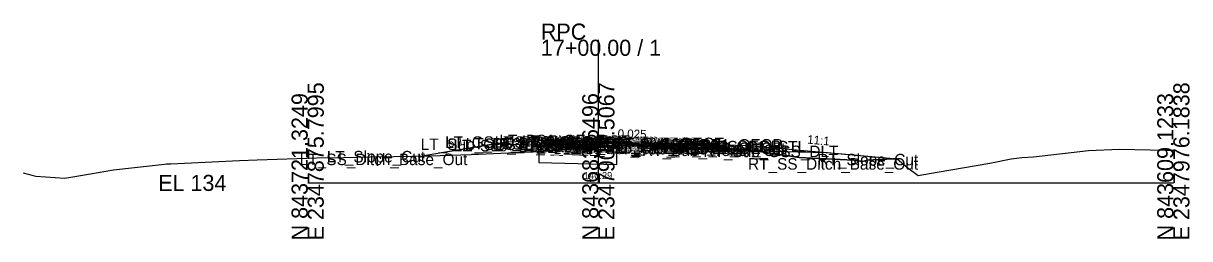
# Model space of a CAD drawing. Extents: x -26 to 203, y -10 to 7538.
# Drawn here: x 0 to 202.8, y 3490.3 to 3527.7 of the extents above; entities that cross this region are included whole.
import ezdxf

# ---------------------------------------------------------------- set-up
doc = ezdxf.new("R2010")
doc.units = 0
for name, color, linetype in [('Default', 7, 'Continuous'), ('Exist CMT Pavement', 7, 'Continuous'), ('Exist Cross Section Cell', 7, 'Continuous'), ('Exist XS Center Line Elevation Label', 7, 'Continuous'), ('Exist XS Ground Line', 7, 'Continuous'), ('Prop CMT Pvmt Course 1', 7, 'Continuous'), ('Prop CMT Pvmt Course 1 Wedge', 7, 'Continuous'), ('Prop CMT Pvmt Course 2', 7, 'Continuous'), ('Prop CMT Pvmt Course 2 Wedge', 7, 'Continuous'), ('Prop CMT Pvmt Course 3', 7, 'Continuous'), ('Prop CMT Pvmt Course 3 Wedge', 7, 'Continuous'), ('Prop CMT Pvmt Surface', 7, 'Continuous'), ('Prop CMT Pvmt Surface Shoulder', 7, 'Continuous'), ('Prop CMT Pvmt Wedge Surface 1', 7, 'Continuous'), ('Prop CMT Pvmt Wedge Surface 2', 7, 'Continuous'), ('Prop CMT Pvmt Wedge Surface 3', 7, 'Continuous'), ('Prop CMT Shld Paved Course 1', 7, 'Continuous'), ('Prop CMT Shld Paved Course 2', 7, 'Continuous'), ('Prop CMT Shld Paved Course 3', 7, 'Continuous'), ('Prop CMT Slope Grass', 7, 'Continuous'), ('Prop CMT Subgrade Earthwork', 7, 'Continuous'), ('Prop Road Sect_ Recs - UC (Outline)', 7, 'Continuous'), ('Prop XS Earthwork Shape', 7, 'Continuous'), ('Prop XS SE Text', 7, 'Continuous'), ('Prop XS Side Slope Text', 7, 'Continuous'), ('Scratch_Level_0', 7, 'Continuous')]:
    doc.layers.add(name, color=color, linetype=linetype)

msp = doc.modelspace()

# ---------------------------------------------------------------- linework, layer by layer
at = {"layer": 'Exist CMT Pavement'}
msp.add_line((100, 3506.29), (106.87, 3506.63), dxfattribs=at)
at = {"layer": 'Exist Cross Section Cell'}
for p, q in [((100, 3500), (100, 3524.89)), ((49.45, 3500), (100, 3500)), ((100, 3500), (200, 3500))]:
    msp.add_line(p, q, dxfattribs=at)
at = {"layer": 'Exist XS Ground Line'}
msp.add_lwpolyline([(0, 3501.76), (1.7, 3501.28), (2.18, 3501.16), (7.2, 3500.82), (11.7, 3501.57), (15.66, 3502.28), (24.53, 3503.25), (24.9, 3503.29), (25.68, 3503.34), (37.62, 3503.88), (40.68, 3503.99), (51.04, 3504.33), (55.68, 3504.44), (60.31, 3504.51), (64.46, 3504.59), (70.67, 3504.72), (77.88, 3504.96), (85.67, 3505.3), (88.64, 3505.4), (99.25, 3506.23), (100, 3506.29), (103.19, 3506.55), (104.54, 3506.63), (105.1, 3506.63), (106.89, 3506.63), (107.48, 3506.61), (108.82, 3506.56), (109.81, 3506.53), (110.67, 3506.5), (111.56, 3506.46), (112.57, 3506.41), (113.36, 3506.38), (114.05, 3506.34), (115.12, 3506.29), (116.33, 3506.23), (117.44, 3506.18), (120.06, 3506.03), (120.72, 3506), (122.64, 3505.91), (123.07, 3505.9), (124.14, 3505.81), (125.84, 3505.69), (126.42, 3505.68), (129.93, 3505.16), (134.9, 3504.4), (144.41, 3503.93), (145.95, 3503.71), (146.75, 3503.97), (151.21, 3504.17), (151.99, 3504.18), (153.8, 3502.61), (155.64, 3501.26), (158.95, 3501.88), (168.1, 3503.44), (171.81, 3504.21), (173.63, 3504.39), (175.66, 3504.52), (185.23, 3505.61), (190.66, 3505.86), (198.65, 3505.68), (200, 3505.68)], dxfattribs=at)
at = {"layer": 'Prop CMT Pvmt Course 1'}
for p, q in [((100, 3507.17), (96, 3507.27)), ((96, 3507.27), (96, 3507.02)), ((100, 3506.92), (100, 3507.17)), ((100, 3507.17), (112, 3506.87)), ((100, 3506.92), (100, 3507.17)), ((96, 3507.02), (100, 3506.92)), ((100, 3506.92), (100, 3507.04)), ((100, 3507.04), (100, 3507.04)), ((100, 3507.04), (100, 3506.92)), ((106.88, 3506.87), (100, 3507.04)), ((100, 3507.04), (100, 3506.92)), ((100, 3506.92), (100, 3506.92)), ((100, 3506.92), (100, 3506.92)), ((106.88, 3506.75), (106.88, 3506.87)), ((112, 3506.62), (106.88, 3506.75)), ((112, 3506.87), (112, 3506.62))]:
    msp.add_line(p, q, dxfattribs=at)
at = {"layer": 'Prop CMT Pvmt Course 1 Wedge'}
msp.add_line((100, 3507.04), (106.88, 3506.87), dxfattribs=at)
at = {"layer": 'Prop CMT Pvmt Course 2'}
for p, q in [((100, 3506.92), (96, 3507.02)), ((96, 3507.02), (96, 3506.68)), ((96, 3506.68), (100, 3506.58)), ((100, 3506.58), (100, 3506.92)), ((106.88, 3506.41), (106.88, 3506.75)), ((106.88, 3506.75), (112, 3506.62)), ((112, 3506.28), (106.88, 3506.41)), ((112, 3506.62), (112, 3506.28))]:
    msp.add_line(p, q, dxfattribs=at)
at = {"layer": 'Prop CMT Pvmt Course 2 Wedge'}
msp.add_line((100, 3506.92), (106.88, 3506.75), dxfattribs=at)
at = {"layer": 'Prop CMT Pvmt Course 3'}
for p, q in [((100, 3506.58), (96, 3506.68)), ((96, 3506.68), (96, 3506.35)), ((96, 3506.35), (100, 3506.25)), ((100, 3506.25), (100, 3506.58)), ((106.88, 3506.41), (112, 3506.28)), ((106.88, 3506.08), (106.88, 3506.41)), ((112, 3505.95), (106.88, 3506.08)), ((112, 3506.28), (112, 3505.95))]:
    msp.add_line(p, q, dxfattribs=at)
at = {"layer": 'Prop CMT Pvmt Course 3 Wedge'}
msp.add_line((100, 3506.58), (106.88, 3506.41), dxfattribs=at)
at = {"layer": 'Prop CMT Pvmt Surface'}
for q in [(96, 3507.27), (112, 3506.87)]:
    msp.add_line((100, 3507.17), q, dxfattribs=at)
at = {"layer": 'Prop CMT Pvmt Surface Shoulder'}
for p, q in [((96, 3507.27), (92, 3507.37)), ((112, 3506.87), (122, 3506.62))]:
    msp.add_line(p, q, dxfattribs=at)
at = {"layer": 'Prop CMT Pvmt Wedge Surface 1'}
for p, q in [((100, 3507.04), (106.88, 3506.87)), ((106.88, 3506.87), (106.88, 3506.75)), ((106.88, 3506.75), (112, 3506.62)), ((112, 3506.62), (112, 3506.87))]:
    msp.add_line(p, q, dxfattribs=at)
at = {"layer": 'Prop CMT Pvmt Wedge Surface 2'}
for p, q in [((100, 3506.92), (112, 3506.62)), ((112, 3506.62), (112, 3506.87))]:
    msp.add_line(p, q, dxfattribs=at)
at = {"layer": 'Prop CMT Pvmt Wedge Surface 3'}
for p, q in [((100, 3506.58), (112, 3506.28)), ((112, 3506.28), (112, 3506.87))]:
    msp.add_line(p, q, dxfattribs=at)
at = {"layer": 'Prop CMT Shld Paved Course 1'}
for p, q in [((92, 3507.37), (91.76, 3507.12)), ((91.76, 3507.12), (96, 3507.02)), ((96, 3507.27), (92, 3507.37)), ((96, 3507.02), (96, 3507.27)), ((112, 3506.87), (122, 3506.62)), ((112, 3506.62), (112, 3506.87)), ((122.26, 3506.36), (112, 3506.62)), ((122, 3506.62), (122.26, 3506.36))]:
    msp.add_line(p, q, dxfattribs=at)
at = {"layer": 'Prop CMT Shld Paved Course 2'}
for p, q in [((91.76, 3507.12), (91.43, 3506.8)), ((96, 3507.02), (91.76, 3507.12)), ((91.43, 3506.8), (96, 3506.68)), ((96, 3506.68), (96, 3507.02)), ((112, 3506.62), (122.26, 3506.36)), ((112, 3506.28), (112, 3506.62)), ((122.6, 3506.02), (112, 3506.28)), ((122.26, 3506.36), (122.6, 3506.02))]:
    msp.add_line(p, q, dxfattribs=at)
at = {"layer": 'Prop CMT Shld Paved Course 3'}
for p, q in [((90.93, 3506.81), (90.61, 3506.49)), ((90.61, 3506.49), (96, 3506.35)), ((91.43, 3506.8), (90.93, 3506.81)), ((96, 3506.68), (91.43, 3506.8)), ((96, 3506.35), (96, 3506.68)), ((112, 3506.28), (122.6, 3506.02)), ((112, 3505.95), (112, 3506.28)), ((123.44, 3505.67), (112, 3505.95)), ((122.6, 3506.02), (123.1, 3506.01)), ((123.1, 3506.01), (123.44, 3505.67))]:
    msp.add_line(p, q, dxfattribs=at)
at = {"layer": 'Prop CMT Slope Grass'}
for p, q in [((92, 3507.37), (84, 3507.09)), ((84, 3507.09), (69.64, 3504.7)), ((122, 3506.62), (126, 3506.48)), ((126, 3506.48), (151.99, 3504.18))]:
    msp.add_line(p, q, dxfattribs=at)
at = {"layer": 'Prop CMT Subgrade Earthwork'}
for p, q in [((90.61, 3506.49), (81.72, 3506.71)), ((96, 3506.35), (90.61, 3506.49)), ((100, 3506.25), (96, 3506.35)), ((100, 3506.25), (100, 3506.29)), ((100, 3506.25), (100, 3506.25)), ((106.88, 3506.08), (106.87, 3506.63)), ((106.88, 3506.08), (112, 3505.95)), ((112, 3505.95), (123.44, 3505.67)), ((123.44, 3505.67), (139.85, 3505.26))]:
    msp.add_line(p, q, dxfattribs=at)
at = {"layer": 'Prop Road Sect_ Recs - UC (Outline)'}
msp.add_lwpolyline([(103.19, 3503.17), (103.19, 3503.17), (103.19, 3506.17), (103.19, 3506.17), (103.19, 3506.17), (99.6, 3506.26), (90.63, 3505.55), (89.64, 3505.48), (89.65, 3503.52), (103.19, 3503.17)], close=True, dxfattribs=at)
at = {"layer": 'Prop XS Earthwork Shape'}
for points in [[(70.67, 3504.72), (77.88, 3504.96), (85.67, 3505.3), (88.64, 3505.4), (99.25, 3506.23), (99.6, 3506.26), (96, 3506.35), (90.61, 3506.49), (81.72, 3506.71), (69.64, 3504.7)], [(100, 3506.25), (100, 3506.29), (99.6, 3506.26)], [(100, 3506.29), (103.19, 3506.55), (104.54, 3506.63), (105.1, 3506.63), (106.87, 3506.63)], [(106.88, 3506.08), (112, 3505.95), (123.44, 3505.67), (127.18, 3505.57), (126.42, 3505.68), (125.84, 3505.69), (124.14, 3505.81), (123.07, 3505.9), (122.64, 3505.91), (120.72, 3506), (120.06, 3506.03), (117.44, 3506.18), (116.33, 3506.23), (115.12, 3506.29), (114.05, 3506.34), (113.36, 3506.38), (112.57, 3506.41), (111.56, 3506.46), (110.67, 3506.5), (109.81, 3506.53), (108.82, 3506.56), (107.48, 3506.61), (106.89, 3506.63), (106.87, 3506.63)], [(127.18, 3505.57), (139.85, 3505.26), (151.99, 3504.18), (151.21, 3504.17), (146.75, 3503.97), (145.95, 3503.71), (144.41, 3503.93), (134.9, 3504.4), (129.93, 3505.16)]]:
    msp.add_lwpolyline(points, close=True, dxfattribs=at)

# ---------------------------------------------------------------- texts
at = {"layer": 'Default'}
msp.add_text('-', height=0.0001, dxfattribs=at).set_placement((49.45, 3500))
at = {"layer": 'Exist Cross Section Cell'}
for s, p in [('RPC', (90, 3524.89)), ('17+00.00 / 1', (90, 3522.09)), ('EL 134', (23.45, 3498.6))]:
    msp.add_text(s, height=2.8, dxfattribs=at).set_placement(p)
for s, p in [('E 2347875.7995', (52.25, 3490)), ('E 2347909.5067', (102.8, 3490)), ('E 2347976.1838', (202.8, 3490)), ('N 843721.3249', (49.45, 3490)), ('N 843683.6496', (100, 3490)), ('N 843609.1233', (200, 3490))]:
    msp.add_text(s, height=2.8, rotation=90, dxfattribs=at).set_placement(p)
at = {"layer": 'Exist XS Center Line Elevation Label'}
msp.add_text('140.29', height=1.2, dxfattribs=at).set_placement((97.51, 3500.69))
at = {"layer": 'Prop XS SE Text'}
msp.add_text('0.025', height=1.5, rotation=358.5679, dxfattribs=at).set_placement((103.34, 3507.83))
at = {"layer": 'Prop XS Side Slope Text'}
for s, rotation, p in [('6:1', 9.4623, (73.93, 3506.15)), ('11:1', 354.9547, (136.28, 3506.84))]:
    msp.add_text(s, height=1.5, rotation=rotation, dxfattribs=at).set_placement(p)
at = {"layer": 'Scratch_Level_0'}
for s, p in [('LT_Sub_OSS_DLT', (69.12, 3505.71)), ('LT_GS_OS_CTL', (73.37, 3506.09)), ('LT_Sub_Trench_Out', (74.81, 3505.49)), ('LT_PS3_Shelf_Out', (76.92, 3505.81)), ('LT_PS3_OEOP', (81.67, 3505.8)), ('LT_PS2_OEOP', (81.99, 3506.12)), ('LT_PS1_OEOP', (82.8, 3506.37)), ('LT_Sub_OEOT', (86.08, 3505.35)), ('LT_PV2_OEOT', (86.17, 3506.02)), ('LT_PV3_OEOT', (86.17, 3505.68)), ('LT_PV1_OEOT', (86.74, 3506.27)), ('RT_PV_IEEOP_EG', (88.14, 3505.29)), ('LT_Sub_OEEOP', (89.21, 3505.25)), ('LT_PV2_OEEOP', (89.31, 3505.92)), ('LT_PV3_OEEOP', (89.31, 3505.58)), ('LT_PV1_OEEOP', (89.87, 3506.04)), ('RT_PV2_IEEOP', (89.91, 3505.92)), ('RT_PV3_IEEOP', (89.91, 3505.58)), ('LT_PV2_IEEOP', (89.95, 3505.92)), ('RT_PV1_IEEOP', (90.47, 3506.04)), ('LT_PV1_IEEOP', (90.52, 3506.04)), ('RT_PV_Sub_Tie_Out', (91.77, 3505.63)), ('PV2_PGL', (93.91, 3505.92)), ('RT_PV_OEEOP_EG', (94.37, 3505.63)), ('PV1_PGL', (94.47, 3506.17)), ('RT_Sub_OEEOP', (96.04, 3505.08)), ('RT_PV2_OEEOP', (96.14, 3505.75)), ('RT_PV3_OEEOP', (96.14, 3505.41)), ('RT_PV1_OEEOP', (96.7, 3505.87)), ('RT_PV2_OEOT', (102.13, 3505.62)), ('RT_PV3_OEOT', (102.13, 3505.28)), ('RT_PV1_OEOT', (102.69, 3505.87)), ('RT_PS3_Shelf_Out', (109.04, 3505.01)), ('RT_PS2_OEOP', (112.45, 3505.36)), ('RT_PS1_OEOP', (112.76, 3505.62)), ('RT_GS_OS_CTL', (115.32, 3505.3)), ('LT_SS_Ditch_Base_Out', (48.08, 3503.09)), ('LT_Slope_Cut', (52.79, 3503.56)), ('RT_Sub_OEOT', (102.03, 3504.95)), ('RT_Sub_Trench_Out', (107.6, 3504.67)), ('RT_PS3_OEOP', (112.79, 3505.02)), ('RT_Sub_OSS_DLT', (118.27, 3504.48)), ('RT_Slope_Cut', (138.09, 3503.05)), ('RT_SS_Ditch_Base_Out', (126.03, 3502.3))]:
    msp.add_text(s, height=2, dxfattribs=at).set_placement(p)

doc.saveas('drawing.dxf')
